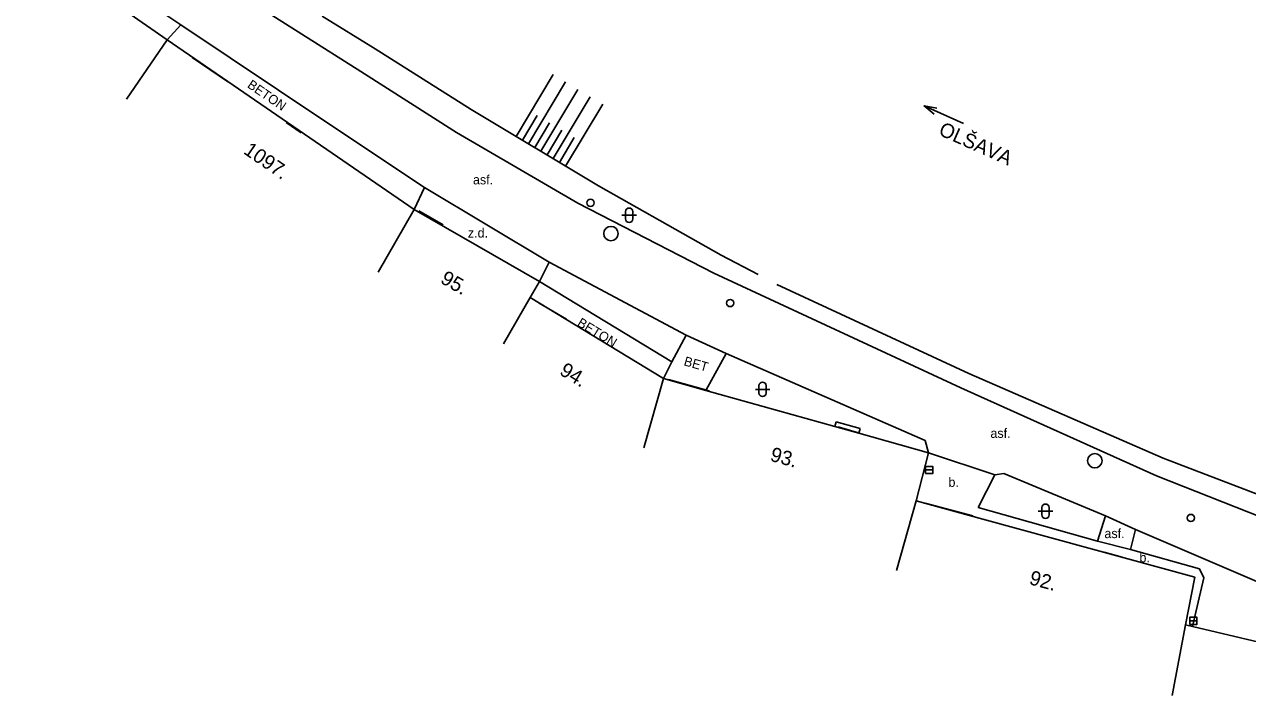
# Model space of a CAD drawing. Extents: x -539244 to -537359, y -1183785 to -1181851.
# Drawn here: x -538160.3 to -538075.4, y -1183541.4 to -1183494.9 of the extents above; entities that cross this region are included whole.
import ezdxf

# ---------------------------------------------------------------- set-up
doc = ezdxf.new("R2010")
doc.units = 0
for name, color, linetype in [('Vrstva 10', 7, 'Continuous'), ('Vrstva 11', 7, 'Continuous'), ('Vrstva 15', 7, 'Continuous'), ('Vrstva 27', 7, 'Continuous'), ('Vrstva 28', 7, 'Continuous'), ('Vrstva 36', 7, 'Continuous'), ('Vrstva 40', 7, 'Continuous'), ('Vrstva 45', 7, 'Continuous'), ('Vrstva 47', 7, 'Continuous'), ('Vrstva 5', 7, 'Continuous'), ('Vrstva 6', 7, 'Continuous'), ('Vrstva 7', 7, 'Continuous'), ('Vrstva 9', 7, 'Continuous')]:
    doc.layers.add(name, color=color, linetype=linetype)

msp = doc.modelspace()

# ---------------------------------------------------------------- linework, layer by layer
at = {"layer": 'Vrstva 10'}
for p, q in [((-538136.93, -1183498.14), (-538147.19, -1183491.63)), ((-538149.42, -1183494.89), (-538153.87, -1183491.91)), ((-538139.22, -1183501.72), (-538149.42, -1183494.89)), ((-538130.3, -1183502.37), (-538136.93, -1183498.14)), ((-538132.52, -1183506.18), (-538139.22, -1183501.72)), ((-538121.88, -1183507.27), (-538130.3, -1183502.37)), ((-538123.87, -1183511.35), (-538132.52, -1183506.18)), ((-538112.45, -1183512.12), (-538121.88, -1183507.27)), ((-538114.37, -1183516.42), (-538123.87, -1183511.35)), ((-538095.32, -1183520.07), (-538112.45, -1183512.12)), ((-538111.59, -1183517.7), (-538114.37, -1183516.42)), ((-538097.79, -1183523.73), (-538111.59, -1183517.7)), ((-538081.74, -1183526.17), (-538095.32, -1183520.07)), ((-538104.065, -1183522.76), (-538103.97, -1183522.422)), ((-538103.97, -1183522.422), (-538102.3, -1183522.89)), ((-538102.395, -1183523.228), (-538102.3, -1183522.89)), ((-538092.96, -1183526.11), (-538092.35, -1183526.01)), ((-538092.35, -1183526.01), (-538085.28, -1183528.95)), ((-538068.57, -1183531.39), (-538081.74, -1183526.17)), ((-538085.28, -1183528.95), (-538083.2, -1183529.9)), ((-538070.06, -1183535.56), (-538083.2, -1183529.9))]:
    msp.add_line(p, q, dxfattribs=at)
msp.add_lwpolyline([(-538092.96, -1183526.11), (-538097.57, -1183524.58), (-538097.79, -1183523.73)], dxfattribs=at)
at = {"layer": 'Vrstva 11'}
for p, q in [((-538150.37, -1183495.93), (-538149.42, -1183494.89)), ((-538133.25, -1183507.71), (-538132.52, -1183506.18)), ((-538124.55, -1183512.69), (-538123.87, -1183511.35)), ((-538124.55, -1183512.69), (-538115.364, -1183518.28)), ((-538115.364, -1183518.28), (-538114.37, -1183516.42)), ((-538113.005, -1183520.255), (-538111.59, -1183517.7)), ((-538115.95, -1183519.43), (-538115.364, -1183518.28)), ((-538094.13, -1183528.37), (-538092.96, -1183526.11)), ((-538085.85, -1183530.71), (-538094.13, -1183528.37)), ((-538083.2, -1183529.9), (-538083.55, -1183531.3))]:
    msp.add_line(p, q, dxfattribs=at)
for points in [[(-538083.55, -1183531.3), (-538085.85, -1183530.71), (-538085.28, -1183528.95)], [(-538083.55, -1183531.3), (-538078.78, -1183532.63), (-538078.47, -1183533.26), (-538079.265, -1183536.62)]]:
    msp.add_lwpolyline(points, dxfattribs=at)
at = {"layer": 'Vrstva 15'}
for p, q in [((-538126.165, -1183502.632), (-538123.595, -1183498.343)), ((-538125.307, -1183503.146), (-538122.737, -1183498.857)), ((-538124.449, -1183503.66), (-538121.88, -1183499.371)), ((-538123.591, -1183504.174), (-538121.022, -1183499.885)), ((-538122.734, -1183504.688), (-538120.164, -1183500.399)), ((-538125.736, -1183502.889), (-538124.708, -1183501.174)), ((-538124.878, -1183503.403), (-538123.85, -1183501.687)), ((-538124.02, -1183503.917), (-538122.992, -1183502.201)), ((-538123.162, -1183504.431), (-538122.135, -1183502.715))]:
    msp.add_line(p, q, dxfattribs=at)
at = {"layer": 'Vrstva 27'}
for p, q in [((-538097.77, -1183525.77), (-538097.27, -1183525.77)), ((-538079.45, -1183536.24), (-538078.95, -1183536.24))]:
    msp.add_line(p, q, dxfattribs=at)
for points in [[(-538097.77, -1183526.02), (-538097.27, -1183526.02), (-538097.27, -1183525.52), (-538097.77, -1183525.52)], [(-538079.45, -1183536.49), (-538078.95, -1183536.49), (-538078.95, -1183535.99), (-538079.45, -1183535.99)]]:
    msp.add_lwpolyline(points, close=True, dxfattribs=at)
for centre in [(-538119.59, -1183509.37), (-538086.03, -1183525.13)]:
    msp.add_circle(centre, 0.5, dxfattribs=at)
at = {"layer": 'Vrstva 28'}
for centre in [(-538121.01, -1183507.24), (-538111.32, -1183514.19), (-538079.37, -1183529.1)]:
    msp.add_circle(centre, 0.25, dxfattribs=at)
at = {"layer": 'Vrstva 36'}
for p, q in [((-538118.578, -1183507.849), (-538118.578, -1183508.35)), ((-538118.077, -1183507.849), (-538118.077, -1183508.35)), ((-538118.827, -1183508.1), (-538117.827, -1183508.1)), ((-538109.574, -1183520.178), (-538108.574, -1183520.178)), ((-538109.325, -1183519.927), (-538109.325, -1183520.428)), ((-538108.824, -1183519.927), (-538108.824, -1183520.428)), ((-538089.948, -1183528.636), (-538088.948, -1183528.636)), ((-538089.699, -1183528.385), (-538089.699, -1183528.886)), ((-538089.198, -1183528.385), (-538089.198, -1183528.886))]:
    msp.add_line(p, q, dxfattribs=at)
for centre, start, end in [((-538118.327, -1183507.85), 0, 180), ((-538118.327, -1183508.35), 180, 0), ((-538109.074, -1183519.928), 0, 180), ((-538109.074, -1183520.428), 180, 0), ((-538089.448, -1183528.386), 0, 180), ((-538089.448, -1183528.886), 180, 0)]:
    msp.add_arc(centre, 0.25, start, end, dxfattribs=at)
at = {"layer": 'Vrstva 45'}
msp.add_line((-538095.131, -1183501.739), (-538097.873, -1183500.521), dxfattribs=at)
msp.add_lwpolyline([(-538097.166, -1183501.087), (-538097.873, -1183500.521), (-538096.979, -1183500.666)], dxfattribs=at)
at = {"layer": 'Vrstva 5'}
for p, q in [((-538153.204, -1183500.049), (-538150.37, -1183495.93)), ((-538133.25, -1183507.71), (-538150.37, -1183495.93)), ((-538135.734, -1183512.049), (-538133.25, -1183507.71)), ((-538124.55, -1183512.69), (-538133.25, -1183507.71)), ((-538125.195, -1183513.818), (-538124.55, -1183512.69)), ((-538127.034, -1183517.029), (-538125.195, -1183513.818)), ((-538125.195, -1183513.818), (-538115.95, -1183519.43)), ((-538117.299, -1183524.245), (-538115.95, -1183519.43)), ((-538113.005, -1183520.255), (-538115.95, -1183519.43)), ((-538104.065, -1183522.76), (-538113.005, -1183520.255)), ((-538102.395, -1183523.228), (-538104.065, -1183522.76)), ((-538097.57, -1183524.58), (-538102.395, -1183523.228)), ((-538098.431, -1183527.922), (-538097.57, -1183524.58)), ((-538099.78, -1183532.736), (-538098.431, -1183527.922)), ((-538098.431, -1183527.922), (-538093.801, -1183529.189)), ((-538093.801, -1183529.189), (-538079.1, -1183533.21)), ((-538079.73, -1183536.51), (-538079.1, -1183533.21)), ((-538080.667, -1183541.421), (-538079.73, -1183536.51))]:
    msp.add_line(p, q, dxfattribs=at)
msp.add_lwpolyline([(-538063, -1183540.47), (-538079.265, -1183536.62), (-538079.73, -1183536.51)], dxfattribs=at)
at = {"layer": 'Vrstva 6'}
for p, q in [((-538146.18, -1183498.83), (-538148.64, -1183497.15)), ((-538141.08, -1183502.38), (-538142.12, -1183501.66)), ((-538131.22, -1183508.76), (-538132.92, -1183507.8)), ((-538122.67, -1183515.32), (-538124.561, -1183514.195)), ((-538112.77, -1183520.28), (-538115.6, -1183519.5)), ((-538102.34, -1183523.21), (-538103.84, -1183522.78)), ((-538094.49, -1183528.96), (-538097.79, -1183528.08)), ((-538084.14, -1183531.81), (-538085.38, -1183531.48))]:
    msp.add_line(p, q, dxfattribs=at)
at = {"layer": 'Vrstva 7'}
msp.add_line((-538160.27, -1183489.04), (-538150.37, -1183495.93), dxfattribs=at)
at = {"layer": 'Vrstva 9'}
for p, q in [((-538139.63, -1183494.28), (-538135.95, -1183496.56)), ((-538135.95, -1183496.56), (-538129.29, -1183500.76)), ((-538129.29, -1183500.76), (-538120.46, -1183506.05)), ((-538120.46, -1183506.05), (-538111.94, -1183510.86)), ((-538111.94, -1183510.86), (-538109.37, -1183512.2)), ((-538108.09, -1183512.91), (-538094.76, -1183519.08)), ((-538094.76, -1183519.08), (-538081.28, -1183524.96)), ((-538081.28, -1183524.96), (-538068.32, -1183529.94))]:
    msp.add_line(p, q, dxfattribs=at)

# ---------------------------------------------------------------- texts
at = {"layer": 'Vrstva 40'}
for s, rotation, p in [('BETON', 325.46875, (-538144.865, -1183499.191)), ('BETON', 328.74096, (-538121.983, -1183515.732)), ('BET', 344.34624, (-538114.581, -1183518.506))]:
    msp.add_text(s, height=0.65, rotation=rotation, dxfattribs=at).set_placement(p)
for s, p in [('asf.', (-538129.162, -1183505.96)), ('z.d.', (-538129.518, -1183509.65)), ('asf.', (-538093.27, -1183523.548)), ('b.', (-538096.181, -1183526.942)), ('asf.', (-538085.364, -1183530.499)), ('b.', (-538082.934, -1183532.172))]:
    msp.add_text(s, height=0.65, dxfattribs=at).set_placement(p)
at = {"layer": 'Vrstva 45'}
msp.add_text('OLŠAVA', height=1, rotation=336.04914, dxfattribs=at).set_placement((-538096.931, -1183502.496))
at = {"layer": 'Vrstva 47'}
for s, rotation, p in [('1097.', 325.46875, (-538145.144, -1183503.774)), ('95.', 330.21258, (-538131.489, -1183512.751)), ('94.', 328.74096, (-538123.227, -1183519.108)), ('93.', 344.34624, (-538108.612, -1183525.121)), ('92.', 344.701, (-538090.635, -1183533.684))]:
    msp.add_text(s, height=1, rotation=rotation, dxfattribs=at).set_placement(p)

doc.saveas('drawing.dxf')
